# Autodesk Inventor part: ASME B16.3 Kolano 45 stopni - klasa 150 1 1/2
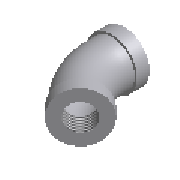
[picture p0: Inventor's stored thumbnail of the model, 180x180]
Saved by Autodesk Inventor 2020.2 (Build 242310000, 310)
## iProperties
Manager: www.cadconsulting.pl
Company: Fabian Stasiak CAD Consulting
NAME: PIPING: ASME B16.3 45 Deg Elbow - Class 150
DATA: <meta><inlinegroups number="0" deflen="0"></inlinegroups><connections number="2"></connections><angles><a>2.35619449019234</a></angles></meta>
Created: 2014-02
Part Number: ASME B16.3 Kolano 45 stopni - klasa 150 1 1/2
Material: Żelazo, ciągliwe
Description: Kolano 45º ze stali zgrzewnej, gwintowane - klasa 150
Document SubType Name: Modeling
Standard: ASME B16.3
Designer: F.Stasiak
Standard Revision: 1988
Standards Organization: ANSI
Language: pl-PL
Size Designation: 1 1/2
Categories: <MemberInstance><Categories><Category DisplayName="Rury cienko- i grubościenne" InternalName="4347fa0f-2144-441d-94cd-e3e15c92b736" Mnemonic="TUBEANDPIPE"><Cate
Density: 7.15 g/cm^3
Appearance: Częściowo polerowana
Catalog Web Link: www.expertbooks.pl
IsCustomPart: 0
Author: F.Stasiak
Subject: Zbiór ćwiczeń. Autodesk Inventor 2020. Kurs Professional
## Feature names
1. Revolution1
2. Sweep1
3. Revolution2
## Parameters: MD = 44.52036 mm, C1 = 36.322 mm, B = 17.78 mm, G = 3.81 mm, F1 = 50.038 mm, d0 = 44.52036 mm, d1 = 57.658 mm, d2 = 61.722 mm, d3 = 9.398 mm, d4 = 17.78 mm, d5 = 0.3124 mm, d16 = 90 deg, d6 = 50.038 mm, d7 = 57.658 mm, d8 = 135 deg, d9 = 36.322 mm, d10 = 18.542 mm, d11 = 0, d12 = 0.3124 mm, d13 = 17.78 mm, d14 = 9.398 mm, d15 = 44.52036 mm, d17 = 57.658 mm, d18 = 61.722 mm, d51 = 90 deg, P = 2.20871 mm, d58 = 17.78 mm, d59 = 0, d60 = 25.4 mm, d61 = 0, H = 61.722 mm, E1 = 9.398 mm, d62 = 0, Size_Designation = 15 mm
